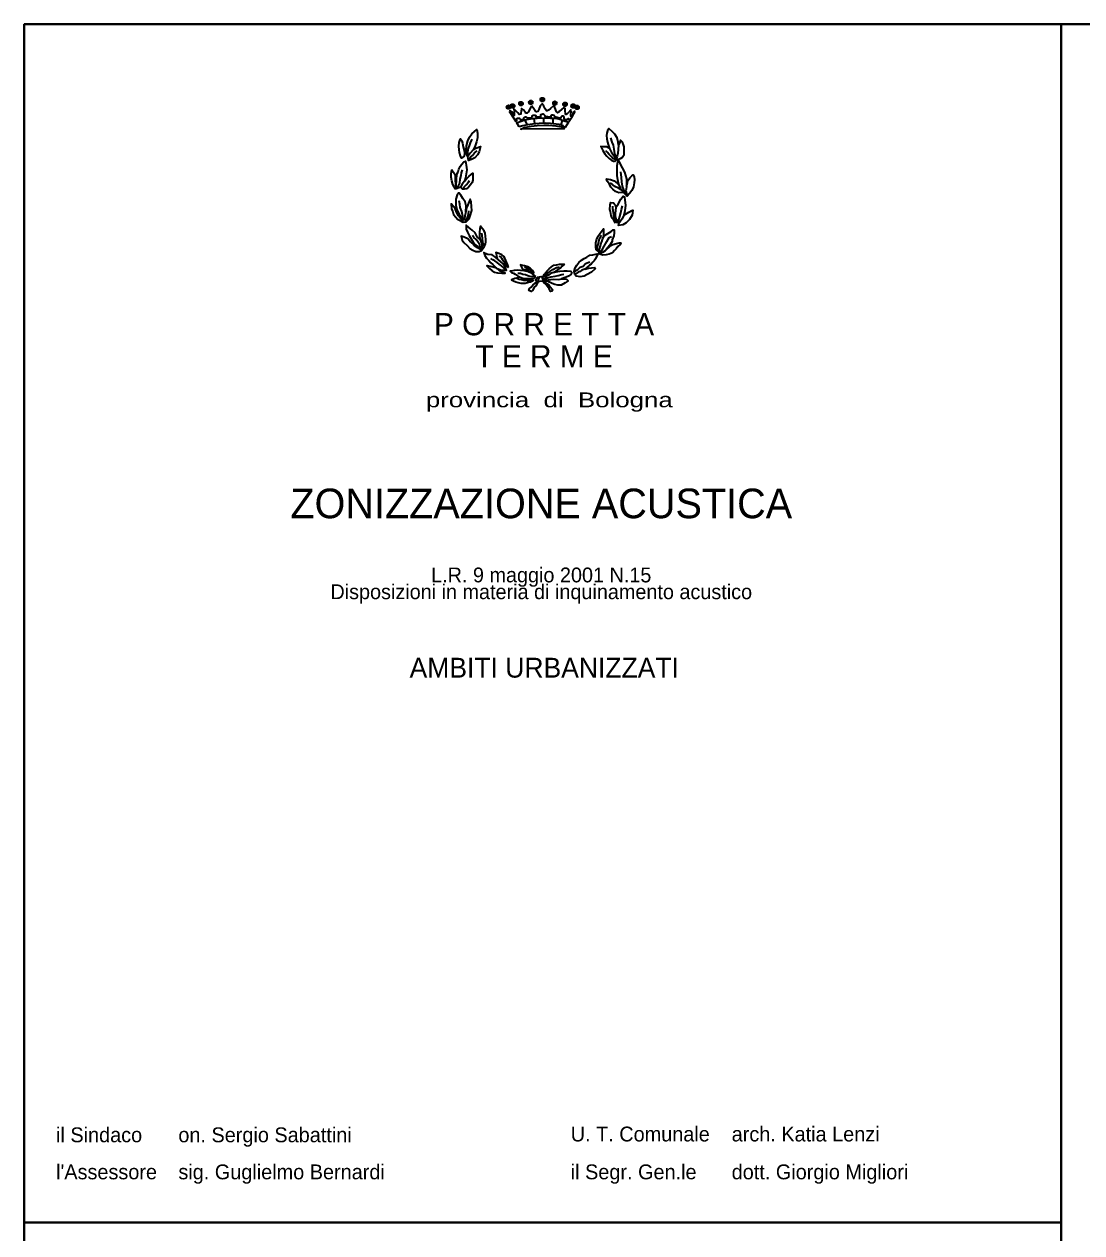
# Model space of a CAD drawing. Extents: x 652791 to 656927, y 889884 to 892405.
# Drawn here: x 652791 to 653862, y 891181 to 892405 of the extents above; entities that cross this region are included whole.
import ezdxf
from ezdxf.enums import TextEntityAlignment as Align

# ---------------------------------------------------------------- set-up
doc = ezdxf.new("R2010")
doc.units = 0
doc.header["$LTSCALE"] = 5.6
doc.layers.add('61', color=7, linetype='Continuous', lineweight=35)

msp = doc.modelspace()

# ---------------------------------------------------------------- hatches: boundary and pattern name
at = {"layer": '61'}
for points in [[(653281.52, 892322.64, 1), (653281.52, 892318.79, 1)], [(653285.66, 892323.74, 1), (653285.66, 892319.9, 1)], [(653294.1, 892326.12, 1), (653294.1, 892322.27, 1)], [(653304.08, 892327.38, 1), (653304.08, 892323.54, 1)], [(653315.74, 892330.23, 1), (653315.74, 892326.38, 1)], [(653328.47, 892326.59, 1), (653328.47, 892322.74, 1)], [(653338.75, 892325.48, 1), (653338.75, 892321.64, 1)], [(653346.89, 892323.74, 1), (653346.89, 892319.9, 1)], [(653350.88, 892322.32, 1), (653350.88, 892318.47, 1)]]:
    msp.add_hatch(color=256, dxfattribs=at).paths.add_polyline_path(points)

# ---------------------------------------------------------------- linework, layer by layer
at = {"layer": '61', "lineweight": 40}
for p, q in [((653841.02, 892404.68), (654894.03, 892404.68)), ((652791.02, 891191.22), (653841.02, 891191.22))]:
    msp.add_line(p, q, dxfattribs=at)
at = {"layer": '61'}
for p, q in [((653305.44, 892310.4), (653305.44, 892310.28)), ((653308.07, 892303.8), (653307.44, 892309.48)), ((653317.09, 892304.43), (653317.09, 892309.8)), ((653326.64, 892303.95), (653326.79, 892309.8)), ((653300.69, 892302.83), (653297.94, 892307.75)), ((653334.92, 892302.35), (653336.29, 892307.43)), ((653228.17, 892241.08), (653227.87, 892237.75)), ((653235.4, 892204.28), (653238.61, 892204.44)), ((653254.11, 892175.37), (653257.02, 892179.81)), ((653257.02, 892179.8), (653254.42, 892182.18)), ((653307.44, 892152.63), (653305.14, 892152.15))]:
    msp.add_line(p, q, dxfattribs=at)
at = {"layer": '61', "lineweight": 40}
msp.add_lwpolyline([(653841.02, 892404.68), (653841.02, 890918.43), (652791.02, 890918.43), (652791.02, 892404.68)], close=True, dxfattribs=at)
at = {"layer": '61'}
for points in [[(653304.82, 892322.13), (653303.62, 892320.08), (653301.29, 892315.65), (653300.37, 892314.7), (653299.17, 892314.7), (653298.54, 892315.48), (653297.62, 892316.43), (653296.72, 892317.85), (653294.57, 892319.43), (653294.24, 892316.75), (653294.09, 892314.7), (653293.94, 892313.43), (653292.42, 892313.1), (653291.04, 892315.03), (653289.02, 892316.9), (653286.89, 892318.83), (653287.07, 892316.28), (653287.34, 892313.75), (653287.19, 892312.33), (653284.74, 892315.95), (653283.34, 892316.9), (653282.12, 892316.75)], [(653349.04, 892316.28), (653348.12, 892316.28), (653347.04, 892315.65), (653346.72, 892314.05), (653346.42, 892312.18), (653345.52, 892310.75), (653344.72, 892311.53), (653344.59, 892313.28), (653344.89, 892315.95), (653344.59, 892317.85), (653341.97, 892315.03), (653340.59, 892313.43), (653339.97, 892313.28), (653339.52, 892313.28), (653339.22, 892314.23), (653338.74, 892316.9), (653338.74, 892319.43), (653337.52, 892320.25), (653335.22, 892318.33), (653333.24, 892316.6), (653332.44, 892315.48), (653331.22, 892315.03), (653330.17, 892315.8), (653329.37, 892317.7), (653328.17, 892321.35), (653326.94, 892321.98), (653324.17, 892319.43), (653321.87, 892317.55), (653320.64, 892316.9), (653319.87, 892316.9), (653318.64, 892318.83), (653317.09, 892321.65), (653315.42, 892324.03), (653313.57, 892321.83), (653312.04, 892318.2), (653311.12, 892316.28), (653309.74, 892315.95), (653308.52, 892317.08), (653306.52, 892320.08), (653304.82, 892322.13)], [(653282.12, 892316.75), (653287.19, 892308.68), (653288.89, 892306), (653289.82, 892306.65), (653289.97, 892307.13), (653289.64, 892308.2), (653289.97, 892309), (653290.57, 892309.65), (653292.42, 892309.48), (653293.34, 892308.68), (653293.64, 892307.55), (653297.02, 892308.85), (653297.02, 892309.33), (653297.02, 892309.8), (653297.32, 892310.1), (653297.94, 892310.58), (653298.24, 892310.75), (653299.17, 892310.75), (653299.77, 892310.4), (653300.37, 892309.8), (653305.44, 892310.28)], [(653305.44, 892310.4), (653305.44, 892310.9), (653305.44, 892311.53), (653305.74, 892312.03), (653306.52, 892312.5), (653307.44, 892312.65), (653308.37, 892312.5), (653309.29, 892312.03), (653309.29, 892310.75), (653314.19, 892310.75), (653314.19, 892311.2), (653314.19, 892312.65), (653314.37, 892313.28), (653315.12, 892313.58), (653316.19, 892313.9), (653317.27, 892313.28), (653318.19, 892312.33), (653318.19, 892311.38), (653324.62, 892310.9), (653324.62, 892311.2), (653324.62, 892311.7), (653324.92, 892312.5), (653325.42, 892312.8), (653326.47, 892312.8), (653327.54, 892312.5), (653328.17, 892311.05), (653334.44, 892309.65), (653334.44, 892310.28), (653335.07, 892311.05), (653335.84, 892311.7), (653337.07, 892311.7), (653337.52, 892310.58), (653337.52, 892308.85), (653341.04, 892307.88), (653341.22, 892308.53), (653342.14, 892309), (653343.34, 892307.55), (653342.89, 892306.33), (653346.42, 892311.38), (653349.04, 892316.28)], [(653239.07, 892281.55), (653240.44, 892286.45), (653241.82, 892290.28), (653244.29, 892293.55), (653246.89, 892296.1), (653249.34, 892298.03), (653250.12, 892294.2), (653250.12, 892289.63), (653249.19, 892285.5), (653247.82, 892281.55), (653245.99, 892277.75), (653248.42, 892279.2), (653253.04, 892280.93), (653252.89, 892279.48), (653251.64, 892275.4), (653250.12, 892272.38), (653247.37, 892269.38), (653243.97, 892267.65), (653240.92, 892266.53), (653240.29, 892270.65)], [(653240.14, 892270.65), (653240.14, 892274.28), (653240.77, 892278.08), (653241.82, 892281.4), (653242.92, 892284.4), (653244.74, 892288.35)], [(653390.77, 892269.15), (653389.24, 892273.35), (653388.62, 892278.25), (653387.72, 892282.05), (653386.49, 892285.05), (653385.09, 892289.63)], [(653240.14, 892270.65), (653238.77, 892273.68), (653238.47, 892277.13), (653239.07, 892281.55)], [(653245.99, 892277.75), (653242.77, 892274.1), (653240.29, 892270.65)], [(653240.92, 892266.53), (653243.22, 892270.18), (653244.89, 892271.58), (653246.89, 892274.28), (653249.64, 892276.5)], [(653383.87, 892278.88), (653385.87, 892274.78), (653388.02, 892271.63), (653389.07, 892269.23), (653390.14, 892267.18), (653387.09, 892268.75), (653385.27, 892270.65), (653383.42, 892272.7), (653381.24, 892275.08), (653380.04, 892276.53)], [(653392.92, 892282.2), (653392.62, 892277.63), (653392.17, 892273.98), (653391.39, 892271.15), (653390.14, 892267.18)], [(653227.87, 892237.75), (653230.94, 892241.08), (653232.19, 892243.75), (653232.47, 892247.88), (653233.54, 892251.35), (653234.02, 892254.2), (653234.77, 892257.05)], [(653401.79, 892230.65), (653398.89, 892235.4), (653397.04, 892240.6), (653396.29, 892245.08), (653395.82, 892249.33), (653395.22, 892255)], [(653236.77, 892245.83), (653234.62, 892242.65), (653232.94, 892239.65)], [(653234.77, 892237.45), (653236.92, 892240.13), (653238.59, 892242.03), (653240.92, 892244.55), (653242.14, 892246.48)], [(653395.52, 892236.85), (653392.77, 892238.58), (653389.07, 892240.3), (653384.77, 892243.95)], [(653397.97, 892234.13), (653395.52, 892236.85), (653394.74, 892239.2), (653393.07, 892242.38)], [(653401.04, 892240.3), (653400.74, 892237.6), (653400.42, 892236.2), (653401.79, 892230.65)], [(653238.59, 892204.43), (653241.52, 892207.6), (653242.74, 892210.75), (653244.29, 892216.15), (653244.14, 892219.9), (653243.67, 892224.68), (653242.74, 892227.35), (653240.44, 892221.83), (653239.07, 892218.83), (653238.32, 892214.73), (653238.59, 892220.73), (653237.67, 892224.83), (653235.39, 892228), (653233.09, 892231.63), (653231.24, 892233.85), (653229.42, 892231.95), (653228.17, 892227.53), (653228.17, 892224.68), (653228.17, 892220.55), (653229.09, 892217.08), (653231.54, 892212.33), (653234.14, 892208.23), (653235.39, 892204.28), (653234.62, 892205.85), (653232.92, 892207.75), (653230.77, 892210.75), (653228.94, 892214.23), (653227.42, 892218.03), (653223.42, 892222.78), (653223.87, 892217.55), (653224.97, 892214.53), (653225.89, 892212), (653228.02, 892209.33), (653229.69, 892207.28), (653232.47, 892205.7), (653235.39, 892204.28)], [(653235.69, 892206.73), (653235.24, 892209.8), (653234.32, 892214.85), (653232.62, 892218.98), (653232.19, 892222.3), (653231.54, 892225.8)], [(653238.32, 892214.73), (653237.37, 892210.45), (653236.77, 892207.6), (653234.62, 892205.85)], [(653236.77, 892207.6), (653238.59, 892204.43), (653239.69, 892207.75), (653241.04, 892211.85), (653241.22, 892215.65)], [(653389.02, 892204.75), (653388.47, 892208.55), (653387.72, 892214.08), (653387.09, 892217.7), (653387.09, 892220.4)], [(653390.14, 892219), (653389.84, 892215.83), (653389.54, 892212.98), (653389.54, 892210.75), (653390.14, 892207.6)], [(653398.14, 892211.23), (653396.44, 892207.43), (653393.09, 892202.68), (653393.22, 892206.48), (653394.14, 892209.8), (653395.22, 892213.75), (653395.99, 892216.93), (653396.89, 892220.73)], [(653257.02, 892179.8), (653258.07, 892182), (653258.37, 892184.2), (653258.37, 892186.73), (653258.24, 892189.9), (653257.77, 892193.08), (653256.69, 892195.28), (653254.84, 892197.8), (653253.17, 892200.18), (653252.39, 892197.8), (653252.09, 892193.55), (653251.97, 892190.88), (653252.39, 892187.05), (653249.79, 892189.45), (653247.64, 892193.23), (653244.74, 892196.08), (653241.37, 892198.93), (653238.59, 892201.15), (653238.59, 892199.55), (653238.77, 892197.18), (653239.97, 892194.03), (653241.67, 892190.7), (653243.52, 892187.38), (653245.79, 892184.05), (653247.97, 892181.35), (653251.47, 892178.68), (653254.09, 892175.38), (653253.17, 892176.48), (653249.94, 892178.03), (653247.02, 892180.28), (653244.74, 892182.8), (653242.44, 892185), (653240.29, 892187.38), (653236.59, 892189.1), (653233.39, 892190.08), (653234.47, 892185.95), (653236.29, 892183.43), (653239.69, 892180.43), (653242.44, 892177.58), (653245.34, 892175.68)], [(653252.39, 892187.05), (653254.42, 892182.18), (653254.42, 892178.03), (653253.17, 892176.48), (653252.57, 892181.35), (653250.54, 892184.2), (653248.57, 892186.58), (653246.42, 892188.8), (653245.07, 892190.7)], [(653257.02, 892179.8), (653255.47, 892183.73), (653255.17, 892188.03), (653254.42, 892192.93)], [(653373.14, 892173.45), (653371.29, 892178.2), (653372.39, 892181.68), (653373.47, 892187.55), (653374.82, 892189.75), (653375.59, 892191.03)], [(653377.74, 892189.45), (653376.67, 892187.55), (653375.74, 892184.2), (653375.14, 892182.8), (653374.07, 892179.15), (653373.14, 892176.3), (653373.14, 892173.45)], [(653373.92, 892171.9), (653376.04, 892175.53), (653378.19, 892179.8), (653380.97, 892184.7), (653383.42, 892188.65), (653385.74, 892189.75)], [(653245.34, 892175.68), (653248.42, 892174.55), (653251.64, 892174.4), (653254.09, 892175.38)], [(653373.92, 892171.9), (653377.12, 892173.78), (653379.59, 892175.38)], [(653279.57, 892155.45), (653276.79, 892157.98), (653274.34, 892159.85), (653272.04, 892161.48), (653269.89, 892163.2), (653267.59, 892164.93), (653265.59, 892166.03), (653263.74, 892167.45)], [(653281.39, 892158.3), (653280.79, 892160.65), (653279.87, 892162.88), (653278.94, 892165.4), (653277.87, 892167.65), (653276.62, 892169.53), (653274.79, 892171.1), (653271.57, 892172.38), (653268.67, 892173.48), (653268.82, 892172.53), (653269.42, 892170), (653270.04, 892167.33)], [(653270.05, 892167.33), (653276.19, 892161.94), (653277.03, 892160.75), (653279.56, 892159.73), (653281.41, 892158.31)], [(653281.39, 892158.3), (653278.47, 892162.1), (653276.49, 892164.63), (653274.79, 892167.45), (653273.27, 892169.05), (653272.17, 892169.53)], [(653347.87, 892154.18), (653351.57, 892156.23), (653354.14, 892158.75), (653357.07, 892159.73), (653359.52, 892162.25), (653363.84, 892164.15)], [(653281.39, 892158.3), (653279.57, 892159.73), (653277.04, 892160.75)], [(653309.29, 892149.13), (653306.37, 892151.2), (653303.92, 892153.08), (653300.37, 892154.35), (653297.17, 892154.83), (653293.79, 892155.15), (653290.42, 892155.45), (653287.19, 892155.28), (653284.29, 892154.68), (653283.04, 892154.53), (653284.44, 892153.25), (653286.57, 892152.45), (653288.27, 892151.65), (653290.57, 892149.9), (653292.54, 892148.5)], [(653309.29, 892149.13), (653305.44, 892148.8), (653303.14, 892149), (653301.02, 892149.9), (653298.69, 892150.73), (653296.09, 892151.2), (653293.64, 892152.15), (653291.04, 892152.28)], [(653307.44, 892152.63), (653305.62, 892155.15), (653303.47, 892157.68), (653301.02, 892159.1), (653297.62, 892159.88), (653294.39, 892160.68), (653293.47, 892160.98), (653294.24, 892159.25), (653295.79, 892156.73), (653297.62, 892156.25), (653299.62, 892156.1), (653302.14, 892153.73)], [(653306.32, 892152.38), (653303.32, 892155.45), (653300.69, 892157.2), (653297.62, 892158.78)], [(653302.15, 892153.73), (653303.93, 892153.09), (653305.16, 892152.15), (653307.44, 892152.63)], [(653316.04, 892147.7), (653320.79, 892151.83), (653323.39, 892154.18), (653326.47, 892156.4), (653329.99, 892158.3), (653333.24, 892158.78)], [(653316.34, 892144.53), (653320.97, 892147.88), (653324.32, 892148.8), (653328.77, 892149.43), (653331.72, 892150.23), (653335.52, 892151.2), (653337.37, 892151.53)], [(653326.94, 892153.08), (653324.17, 892152.15), (653322.02, 892150.55), (653319.72, 892149), (653318.64, 892147.38), (653316.49, 892145.8)], [(653358.69, 892156.6), (653355.84, 892155.45), (653354.02, 892154.33), (653351.99, 892153.38), (653350.77, 892152.6), (653349.87, 892151.95), (653348.79, 892151.03)], [(653292.56, 892148.52), (653289.79, 892147.55), (653287.79, 892147.08), (653285.67, 892145.98), (653284.44, 892145.65), (653286.57, 892144.7), (653289.02, 892143.75), (653291.34, 892142.98), (653294.09, 892142.5), (653296.24, 892142.33), (653298.39, 892142.5), (653300.87, 892142.98), (653303.77, 892143.75), (653306.52, 892145.03), (653301.92, 892146.9), (653304.07, 892147.08), (653307.59, 892147.38), (653309.29, 892149.13)], [(653289.79, 892147.55), (653292.24, 892146.6), (653294.57, 892146.13), (653297.02, 892145.5), (653300.22, 892145.18), (653303.62, 892145.18), (653306.52, 892145.03)], [(653301.92, 892146.9), (653298.09, 892146.9), (653295.02, 892147.38), (653292.54, 892148.5)], [(653313.14, 892148.8), (653312.22, 892147.38), (653311.42, 892146.13), (653311.12, 892143.9)], [(653316.34, 892144.53), (653321.57, 892145.8), (653326.94, 892146.45), (653332.32, 892146.13), (653335.07, 892146.75)]]:
    msp.add_lwpolyline(points, dxfattribs=at)
for points in [[(653292.42, 892300.63), (653289.82, 892304.88), (653293.34, 892306.15), (653297.94, 892307.75), (653303.77, 892308.85), (653310.67, 892309.65), (653317.89, 892309.8), (653324.02, 892309.65), (653328.94, 892309.33), (653333.54, 892308.38), (653337.84, 892306.95), (653342.14, 892305.35), (653338.74, 892299.98), (653336.89, 892301.88), (653332.32, 892303.15), (653323.89, 892303.95), (653318.79, 892304.43), (653312.64, 892303.95), (653305.74, 892303.3), (653300.69, 892302.83), (653296.09, 892301.73)], [(653297.47, 892299.98), (653304.39, 892301.43), (653310.67, 892302.03), (653317.09, 892302.5), (653322.17, 892302.35), (653329.54, 892301.58), (653334.92, 892300.78), (653337.74, 892298.63), (653293.87, 892298.33)], [(653388.94, 892265.75), (653390.14, 892267.18), (653394.77, 892268.6), (653396.74, 892269.53), (653398.62, 892272.55), (653398.77, 892275.7), (653398.77, 892280.45), (653397.97, 892282.38), (653396.92, 892285.35), (653394.77, 892287.1), (653394.32, 892285.23), (653392.92, 892282.2), (653392.62, 892285.35), (653391.39, 892289.63), (653389.24, 892293.13), (653387.09, 892295.48), (653382.94, 892298.98), (653382.17, 892297.85), (653380.94, 892294.23), (653380.82, 892291.85), (653380.94, 892288.53), (653381.57, 892285.35), (653382.34, 892282.7), (653383.87, 892278.88), (653380.64, 892280.45), (653377.44, 892280.6), (653374.97, 892280.78), (653376.97, 892276.68), (653378.97, 892273.5), (653380.94, 892271.15), (653383.42, 892268.75), (653386.19, 892266.55)], [(653234.14, 892286.45), (653234.94, 892284.25), (653235.69, 892280.6), (653236.62, 892276.83), (653236.92, 892273.95), (653236.44, 892271.13), (653234.02, 892269.05), (653232.94, 892271.43), (653231.87, 892274.6), (653231.37, 892277.43), (653231.09, 892281.08), (653231.37, 892284.88), (653232.47, 892288.03), (653232.94, 892288.68)], [(653227.87, 892237.75), (653225.27, 892242.18), (653224.17, 892245.98), (653223.27, 892249.63), (653223.27, 892253.4), (653224.17, 892257.05), (653227.09, 892252.93), (653227.42, 892250.4), (653227.57, 892245.98), (653228.17, 892241.08), (653228.79, 892245.5), (653228.79, 892248.68), (653229.54, 892253.4), (653230.34, 892255.3), (653231.24, 892257.85), (653232.47, 892260.7), (653233.87, 892262.6), (653236.14, 892265.13), (653237.84, 892265.9), (653238.59, 892261.95), (653239.22, 892257.2), (653238.77, 892253.08), (653237.99, 892249), (653236.77, 892245.83), (653238.92, 892248.03), (653241.22, 892250.55), (653244.14, 892252.63), (653245.22, 892253.9), (653245.22, 892250.25), (653245.22, 892246.78), (653244.59, 892244.23), (653243.04, 892242.03), (653241.07, 892239.48), (653239.07, 892237.93), (653236.77, 892237.45), (653234.77, 892237.45), (653232.94, 892239.65)], [(653397.97, 892234.13), (653393.22, 892234), (653389.67, 892235.23), (653387.22, 892237.6), (653385.22, 892239.68), (653383.69, 892242.53), (653381.54, 892245.85), (653380.62, 892247.9), (653384.92, 892247.28), (653388.47, 892246), (653393.07, 892242.38), (653392.27, 892246.95), (653391.52, 892251.38), (653391.37, 892254.55), (653391.37, 892261.68), (653392.44, 892267.2), (653394.29, 892263.55), (653396.74, 892259.13), (653399.04, 892254.85), (653401.04, 892248.2), (653401.04, 892240.3), (653401.64, 892242.53), (653402.27, 892246.48), (653404.72, 892249.48), (653406.39, 892251.05), (653407.64, 892252.18), (653408.57, 892249.95), (653409.02, 892247.1), (653408.87, 892244.1), (653408.09, 892240), (653406.39, 892236.2), (653404.12, 892233.2), (653401.79, 892230.65)], [(653389.99, 892203.3), (653388.02, 892206.18), (653386.32, 892208.08), (653385.27, 892211.08), (653384.77, 892214.85), (653384.02, 892217.08), (653384.32, 892221.68), (653384.94, 892224.2), (653387.72, 892223.73), (653389.39, 892221.68), (653390.14, 892219), (653392.44, 892222.3), (653395.22, 892227.53), (653397.67, 892230.53), (653399.07, 892229.75), (653399.37, 892226.4), (653399.99, 892221.35), (653399.37, 892215.65), (653398.14, 892211.23), (653403.19, 892214.38), (653406.27, 892216.15), (653407.32, 892216.45), (653406.72, 892211.23), (653403.94, 892206.8), (653400.74, 892203.48), (653397.22, 892201.58), (653392.92, 892200.78), (653393.09, 892202.68), (653390.14, 892207.6), (653390.14, 892204.1)], [(653373.14, 892173.45), (653370.37, 892176.15), (653369.77, 892178.85), (653369.77, 892183.28), (653370.69, 892186.13), (653372.39, 892189.93), (653374.37, 892193.08), (653376.37, 892195.6), (653377.59, 892197.38), (653377.74, 892194.83), (653377.74, 892191.98), (653377.74, 892189.45), (653380.52, 892191.65), (653383.87, 892193.73), (653385.59, 892194.65), (653387.57, 892196.4), (653388.64, 892196.25), (653388.49, 892193.4), (653388.19, 892190.23), (653386.49, 892186.43), (653386.34, 892184.53), (653384.04, 892181.05), (653382.04, 892178.38), (653379.57, 892175.35), (653384.94, 892180.58), (653387.27, 892181.68), (653390.94, 892182.65), (653393.39, 892183.1), (653395.24, 892183.1), (653394.47, 892181.68), (653392.32, 892179.63), (653390.64, 892177.1), (653388.79, 892175.38), (653386.64, 892172.98), (653383.57, 892171.73), (653380.34, 892170.93), (653377.12, 892170.78), (653373.92, 892171.9)], [(653278.94, 892156.88), (653277.87, 892159.58), (653276.19, 892161.93), (653273.87, 892164.15), (653271.42, 892166.2), (653268.67, 892168.4), (653264.97, 892170.93), (653260.69, 892171.28), (653257.94, 892172.53), (653256.54, 892173.33), (653257.44, 892170.48), (653259.29, 892167.78), (653261.44, 892165.25), (653263.44, 892163.03), (653265.77, 892161.15), (653269.42, 892157.5), (653264.52, 892158.93), (653260.07, 892159.85), (653259.47, 892160.03), (653262.07, 892157.33), (653264.97, 892154.98), (653267.44, 892153.55), (653270.49, 892152.75), (653274.79, 892152.45), (653278.04, 892152.6), (653272.34, 892154.98), (653269.42, 892157.5), (653273.42, 892155.93), (653276.62, 892155.6), (653279.57, 892155.45)], [(653316.04, 892147.7), (653318.02, 892151.53), (653320.47, 892154.83), (653322.79, 892157.05), (653325.09, 892159.1), (653327.24, 892160.5), (653329.99, 892160.98), (653333.07, 892161.63), (653335.84, 892161.78), (653337.99, 892161.63), (653337.37, 892160.98), (653335.97, 892159.58), (653334.29, 892157.68), (653331.22, 892155.93), (653326.94, 892153.08), (653329.69, 892153.88), (653333.54, 892154.53), (653337.37, 892154.98), (653340.89, 892154.98), (653344.72, 892154.68), (653345.52, 892153.08), (653344.72, 892151.2), (653342.27, 892149.6), (653339.82, 892148.35), (653335.07, 892146.75), (653340.14, 892146.45), (653341.97, 892144.85), (653338.89, 892142.8), (653334.92, 892140.45), (653331.54, 892140.45), (653328.47, 892141.08), (653325.57, 892142.18), (653323.09, 892143.28), (653321.39, 892144.53), (653316.34, 892144.53), (653316.49, 892145.8)], [(653347.87, 892154.18), (653348.94, 892157.83), (653350.62, 892160.65), (653352.62, 892163.35), (653355.37, 892165.55), (653358.14, 892167.45), (653360.92, 892168.88), (653363.84, 892170.6), (653366.74, 892171.25), (653371.17, 892172.05), (653371.79, 892171.9), (653370.27, 892168.88), (653369.67, 892167.15), (653368.27, 892165.08), (653366.89, 892163.68), (653365.19, 892161.63), (653363.52, 892160.5), (653358.69, 892156.58), (653362.44, 892157.65), (653365.37, 892157.98), (653368.89, 892158.13), (653369.19, 892157), (653365.37, 892153.7), (653361.07, 892151.03), (653357.99, 892149.43), (653354.02, 892148.95), (653349.87, 892149.6), (653348.79, 892151.03)], [(653313.14, 892148.8), (653314.49, 892149.13), (653316.04, 892147.7), (653316.49, 892145.8), (653316.34, 892144.53), (653313.29, 892144.23), (653311.12, 892143.9), (653309.44, 892140.13), (653307.44, 892138.23), (653306.07, 892135.38), (653304.52, 892133.95), (653302.22, 892134.9), (653302.69, 892136.95), (653304.52, 892138.35), (653306.07, 892140.45), (653308.69, 892142.8), (653311.12, 892143.9), (653309.12, 892144.7), (653308.99, 892146.28), (653310.82, 892148.5)], [(653316.34, 892144.53), (653322.17, 892140.75), (653323.69, 892138.68), (653326.17, 892136.15), (653325.24, 892134.43), (653324.02, 892133.95), (653322.64, 892136.63), (653320.79, 892139.33), (653319.12, 892141.55), (653317.42, 892143.1)]]:
    msp.add_lwpolyline(points, close=True, dxfattribs=at)
for centre in [(653281.52, 892320.71), (653285.66, 892321.82), (653294.1, 892324.19), (653304.08, 892325.46), (653315.74, 892328.31), (653328.47, 892324.67), (653338.75, 892323.56), (653346.89, 892321.82), (653350.88, 892320.4)]:
    msp.add_circle(centre, 1.92, dxfattribs=at)

# ---------------------------------------------------------------- texts
for s, height, p in [('P O R R E T T A', 22.56, (653317.48, 892089.61)), ('T E R M E', 22.56, (653317.49, 892057.01)), ('ZONIZZAZIONE ACUSTICA', 30, (653314.64, 891904.36)), ('L.R. 9 maggio 2001 N.15', 15, (653314.64, 891839.42)), ('Disposizioni in materia di inquinamento acustico', 15, (653314.65, 891822.42)), ('AMBITI URBANIZZATI', 20.06, (653317.69, 891742.98))]:
    msp.add_text(s, height=height, dxfattribs=at).set_placement(p, align=Align.CENTER)
at = {"layer": '61', "width": 1.3}
msp.add_text('provincia  di  Bologna', height=15.04, dxfattribs=at).set_placement((653322.79, 892016.71), align=Align.CENTER)
at = {"layer": '61'}
for s, p in [('il Sindaco', (652823.31, 891272.43)), ('on. Sergio Sabattini', (652947.16, 891272.43)), ('U. T. Comunale', (653344.49, 891273.23)), ('arch. Katia Lenzi', (653507.48, 891273.23)), ("l'Assessore", (652823.34, 891234.91)), ('sig. Guglielmo Bernardi', (652947.19, 891234.91)), ('il Segr. Gen.le', (653344.49, 891234.91)), ('dott. Giorgio Migliori', (653507.48, 891234.91))]:
    msp.add_text(s, height=15.04, dxfattribs=at).set_placement(p)

doc.saveas('drawing.dxf')
